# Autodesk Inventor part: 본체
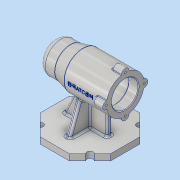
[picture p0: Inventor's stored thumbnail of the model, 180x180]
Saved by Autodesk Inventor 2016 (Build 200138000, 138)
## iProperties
Created: 2019-12
Part Number: 본체
Material: 알루미늄 6061
Document SubType Name: Modeling
Designer: 2-PC10
Density: 2.7 g/cm^3
Appearance: 알루미늄 - 평지
Mass: 724.914 g
Surface Area: 712.64 cm^2
Volume: 268.487 cm^3
Author: 2-PC10
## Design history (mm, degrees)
sketch "스케치1"
  geometry: L1 (0, 0)-(30, 0); L2 (0, 112)-(0, 0); L3 (0, 0)-(30, 0); L4 (30, 0)-(30, 67); L5 (30, 67)-(25, 87); L6 (25, 87)-(25, 112); L7 (25, 112)-(0, 112); L8 (21, 0)-(21, 15); L9 (21, 15)-(21, 15); L10 (24, 18)-(24, 66); L11 (21, 69)-(21, 69); L12 (21, 69)-(21, 80.7); L13 (20.7, 81)-(17.5, 81); L14 (17.5, 81)-(17.5, 98.7); L15 (17.2, 99)-(16, 99); L16 (16, 99)-(16, 102.7); L17 (15.7, 103)-(10.5, 103); L18 (10.5, 103)-(10.5, 103); L19 (7.5, 106)-(0, 106); L20 (21, 0)-(30, 0); A1 r 3 centre (7.5, 103) between (10.5, 103) and (7.5, 106); A2 r 0.3 centre (15.7, 102.7) between (16, 102.7) and (15.7, 103); A3 r 0.3 centre (17.2, 98.7) between (17.5, 98.7) and (17.2, 99); A4 r 0.3 centre (20.7, 80.7) between (21, 80.7) and (20.7, 81); A5 r 3 centre (21, 66) between (24, 66) and (21, 69); A6 r 3 centre (21, 18) between (21, 15) and (24, 18); 4 further points
  constraints: 40 end point, 12 perpendicular, 12 point on circle, 12 tangent, 10 point on line, 6 centre point, 3 equal radius, 3 horizontal, 1 collinear, 1 parallel
  dimensions: "d0" = 112 distance of L2.start L1.start; "d2" = 50 diameter of L6 L2; "d3" = 60 diameter of L4 L2; "d4" = 25 distance of L5.end L6.end; "d5" = 45 distance from line of L7 L4.end; "d7" = 15 distance of L8.start L8.end; "d8" = 54 distance of point (24, 15) point (24, 69); "d9" = 12 distance of L11.end point (21, 81); "d10" = 18 distance of L13.end point (17.5, 99); "d11" = 42 diameter of L8 L2; "d12" = 48 diameter of L10 L2; "d13" = 42 diameter of L12 L2; "d14" = 35 diameter of L14 L2; "d15" = 4 distance between parallel lines of L15 L17; "d16" = 32 diameter of L16 L2; "d17" = 21 diameter of L18 L2; "d18" = 3 distance between parallel lines of L17 L19; "d19" = 3 radius of A1; "d20" = 0.3 radius of A2; "d21" = 3 radius of A5
revolve "회전1" sketch "스케치1" stored, may be unused: angle "d22" = 90 deg
sketch "스케치2"
  geometry: C1 r 6 at (30, 0); 2 further points
  constraints: 1 centre point, 1 horizontal alignment, 1 other
  dimensions: "d23" = 12 diameter of C1
extrude "돌출1" join sketch "스케치2" distance "d24" = 16; taper "d25" = 0 deg
fillet "모깎기1" dims "d26" = 3
fillet "모깎기2" dims "d27" = 1
fillet "모깎기3" dims "d31" = 10
node "작업 평면1"
sketch "스케치3"
  geometry: L1 (6.771, 0)-(29.226, 0) reference; L2 (0, 8)-(0, -5.125); L3 (23.196, 0)-(-23.196, 0); L4 (-56, 32.804)-(-56, 79.196); L5 (-23.196, 112)-(23.196, 112); L6 (56, 79.196)-(56, 32.804); L7 (5.998, 0)-(-5.998, 0) reference; L8 (0, 56)-(67, -11); L9 (56, 32.804)-(43.134, 19.938); L10 (36.062, 12.866)-(23.196, 0); L11 (23.196, 112)-(36.062, 99.134); L12 (43.134, 92.062)-(56, 79.196); L13 (-56, 79.196)-(-43.134, 92.062); L14 (-36.062, 99.134)-(-23.196, 112); L15 (-23.196, 0)-(-36.062, 12.866); L16 (-43.134, 19.938)-(-56, 32.804); A1 r 5 centre (39.598, 16.402) between (43.134, 19.938) and (36.062, 12.866); A2 r 5 centre (39.598, 95.598) between (36.062, 99.134) and (43.134, 92.062); A3 r 5 centre (-39.598, 95.598) between (-43.134, 92.062) and (-36.062, 99.134); A4 r 5 centre (-39.598, 16.402) between (-36.062, 12.866) and (-43.134, 19.938); A5 r 56 centre (0, 56) between (35.908, 98.972) and (-39.598, 16.402); A6 r 56 centre (0, 56) between (-35.908, 13.028) and (42.972, 91.908); 2 further points
  constraints: 28 end point, 16 point on circle, 6 centre point, 2 midpoint, 1 coincident, 1 point on line, 1 vertical, 1 vertical alignment, 26 other
  dimensions: "d37" = 56 distance from line of L1 L8.start; "d40" = 10 diameter of A1; "d43" = 360 deg dimension on L8.start A1.centre (derived)
extrude "돌출2" join sketch "스케치3" distance "d38" = 10; taper "d39" = 0 deg
node "작업 평면2"
sketch "스케치4"
  geometry: L1 (-36, -70)-(-18.584, -22.151); L2 (-56, -80)-(-56, -70) reference; L3 (-56, -70)-(-43.134, -70) reference; L4 (0, 0)-(0, -47); L5 (36, -70)-(18.584, -22.151); L6 (-36.062, -80)-(-36.062, -70) reference; L7 (23.196, -70)-(36.062, -70) reference; L8 (-36.062, -70)-(36.062, -70); A1 r 28.915 centre (0, 0) between (-18.584, -22.151) and (18.584, -22.151); 3 further points
  constraints: 8 end point, 2 point on circle, 2 symmetric about line, 1 centre point, 1 coincident, 1 horizontal, 1 point on line, 1 vertical
  dimensions: "d46" = 20 distance from line of L1.start L2; "d47" = 110 deg angle of L1 L3; "d70" = 28.9147 radius of A1
extrude "돌출3" join sketch "스케치4" stored distance "d49" = 8; taper "d50" = 0 deg
sketch "스케치5"
  geometry: L1 (-70, 99.134)-(-70, 90.598) reference; L2 (-70, 94)-(-25.326, 73.168); L3 (-80, 112)-(-70, 112) reference; L4 (-70, 25)-(-26.997, 25); L5 (-80, 0)-(-70, 0) reference; L6 (-70, 25)-(-70, 94); L7 (-26.997, 25)-(-25.326, 73.168); 3 further points
  constraints: 8 end point, 1 collinear, 1 point on line
  dimensions: "d51" = 115 deg angle of L1 L2; "d52" = 18 distance from line of L2.start L3; "d53" = 25 distance between parallel lines of L4 L5; "d68" = 91.9869 deg angle of L4 L7; "d69" = 43.00307 distance of L4.start L4.end
extrude "돌출4" join sketch "스케치5" stored distance "d54" = 8; taper "d55" = 0 deg
hole "구멍1" diameter "d58" = 3.242; stored, may be unused: countersink angle "d62" = 90 deg, drill point angle "d64" = 118 deg; dims "d56" = 10, "d57" = 10, "d59" = 8, "d60" = 4, "d61" = 2, "d63" = 11
fillet "모깎기4" dims "d71" = 3
chamfer "모따기1" distance "d73" = 1; stored, may be unused: second distance "d74" = 2, angle "d75" = 45 deg
fillet "모깎기6" dims "d76" = 3
node "작업 평면3"
sketch "스케치6"
  geometry: L1 (6.771, 0)-(29.226, 0) reference; 2 further points
  constraints: 1 vertical alignment, 1 other
  dimensions: "d78" = 41 distance from line of L1 point (0, 41)
feature "엠보싱1" sketch "스케치6" dims "d0" = 112, "d2" = 50, "d3" = 60, "d4" = 25, "d5" = 45, "d7" = 15, "d8" = 54, "d9" = 12, "d10" = 18, "d11" = 42, "d12" = 48, "d13" = 42, "d14" = 35, "d15" = 4, "d16" = 32, "d17" = 21, "d18" = 3, "d19" = 3, "d20" = 0.3, "d21" = 3, "d79" = 0.5, "d80" = 0
fillet "모깎기7" dims "d81" = 3
fillet "모깎기8" dims "d82" = 3
node "솔리드1"
pattern_circular "원형 패턴1" dims "d29" = 360 deg
pattern_circular "원형 패턴2" dims angle "d66" = 360 deg
other parameters: "d36" = 112, "d45" = 56, "d48" = 8, "d77" = 53
